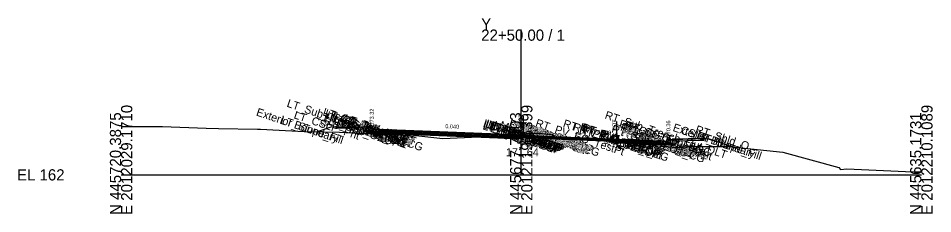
# Model space of a CAD drawing. Extents: x -26 to 3203, y -10 to 9532.
# Drawn here: x 974.3 to 1202.8, y 6490.3 to 6539.1 of the extents above; entities that cross this region are included whole.
import ezdxf

# ---------------------------------------------------------------- set-up
doc = ezdxf.new("R2010")
doc.units = 0
for name, color, linetype in [('Default', 7, 'Continuous'), ('Exist Cross Section Cell', 7, 'Continuous'), ('Exist XS Center Line Elevation Label', 7, 'Continuous'), ('Exist XS Ground Line', 7, 'Continuous'), ('Prop CMT Conc Surface', 7, 'Continuous'), ('Prop CMT Concrete Structures', 7, 'Continuous'), ('Prop CMT Pvmt Course 1', 7, 'Continuous'), ('Prop CMT Pvmt Course 1 CG', 7, 'Continuous'), ('Prop CMT Pvmt Course 1 Wedge', 7, 'Continuous'), ('Prop CMT Pvmt Course 2', 7, 'Continuous'), ('Prop CMT Pvmt Course 2 Wedge', 7, 'Continuous'), ('Prop CMT Pvmt Course 3', 7, 'Continuous'), ('Prop CMT Pvmt Course 3 Wedge', 7, 'Continuous'), ('Prop CMT Pvmt Surface', 7, 'Continuous'), ('Prop CMT Pvmt Wedge Surface 1', 7, 'Continuous'), ('Prop CMT Pvmt Wedge Surface 2', 7, 'Continuous'), ('Prop CMT Pvmt Wedge Surface 3', 7, 'Continuous'), ('Prop CMT Slope Grass', 7, 'Continuous'), ('Prop CMT Subgrade Earthwork', 7, 'Continuous'), ('Prop XS Hydro Elevations', 7, 'Continuous'), ('Prop XS Label Text', 7, 'Continuous'), ('Prop XS SE Text', 7, 'Continuous'), ('Prop XS Side Slope Text', 7, 'Continuous'), ('Scratch_Level_0', 7, 'Continuous')]:
    doc.layers.add(name, color=color, linetype=linetype)

msp = doc.modelspace()

# ---------------------------------------------------------------- linework, layer by layer
at = {"layer": 'Exist Cross Section Cell'}
for p, q in [((1100, 6500), (1100, 6536.29)), ((1000, 6500), (1100, 6500)), ((1100, 6500), (1200, 6500))]:
    msp.add_line(p, q, dxfattribs=at)
at = {"layer": 'Exist XS Ground Line'}
msp.add_lwpolyline([(1000, 6512.07), (1003.64, 6512.06), (1010.33, 6512.1), (1021.27, 6511.7), (1024.36, 6511.59), (1034.12, 6511.4), (1034.82, 6511.39), (1045.76, 6510.83), (1050.58, 6510.76), (1054.55, 6510.69), (1066.17, 6510.09), (1074.44, 6509.73), (1080.45, 6509.07), (1089.43, 6509.51), (1098.06, 6509.69), (1099, 6509.67), (1100.05, 6509.64), (1100.49, 6509.62), (1101.28, 6509.58), (1102.65, 6509.51), (1104.5, 6509.42), (1105.41, 6509.37), (1106.4, 6509.32), (1107.61, 6509.26), (1108.17, 6509.22), (1109.75, 6509.14), (1110.93, 6509.07), (1111.37, 6509.05), (1112.14, 6509.01), (1112.79, 6508.98), (1113.68, 6508.93), (1114.97, 6508.86), (1116.44, 6508.78), (1116.96, 6508.75), (1118.1, 6508.69), (1118.84, 6508.65), (1119.19, 6508.63), (1120.73, 6508.53), (1121.95, 6508.44), (1123.84, 6508.32), (1124.4, 6508.27), (1124.95, 6508.18), (1138.53, 6506.87), (1143.3, 6507.09), (1151.81, 6507.06), (1165.4, 6505.69), (1179.39, 6501.88), (1179.81, 6501.37), (1181.41, 6501.47), (1196.07, 6500.83), (1198.26, 6500.74), (1200, 6500.75)], dxfattribs=at)
at = {"layer": 'Prop CMT Conc Surface'}
for points in [[(1058.75, 6511.9), (1053.75, 6512)], [(1062.66, 6511.32), (1062.65, 6511.82), (1062.15, 6511.82)], [(1064.66, 6511.32), (1062.66, 6511.32)], [(1136.75, 6508.36), (1136.75, 6508.86), (1137.25, 6508.86)], [(1134.75, 6508.52), (1136.75, 6508.36)]]:
    msp.add_lwpolyline(points, dxfattribs=at)
at = {"layer": 'Prop CMT Concrete Structures'}
for points in [[(1053.75, 6511.67), (1053.75, 6512)], [(1053.75, 6512), (1058.75, 6511.9)], [(1058.75, 6511.57), (1053.75, 6511.67)], [(1058.75, 6511.9), (1058.75, 6511.57)], [(1064.66, 6511.32), (1062.66, 6511.32), (1062.65, 6511.82), (1062.15, 6511.82)], [(1062.15, 6511.82), (1062.16, 6510.84), (1064.66, 6510.74)], [(1064.66, 6510.74), (1064.66, 6511.32)], [(1108.33, 6509.57), (1108.32, 6509.74), (1107.57, 6509.99), (1104.55, 6510.35), (1101.54, 6510.29), (1100.79, 6510.04), (1100.78, 6509.88)], [(1100.78, 6509.88), (1108.33, 6509.57)], [(1134.75, 6508.52), (1136.75, 6508.36), (1136.75, 6508.86), (1137.25, 6508.86)], [(1137.25, 6508.86), (1137.25, 6507.83), (1134.75, 6507.93)], [(1145.75, 6509.04), (1137.75, 6508.88)], [(1137.75, 6508.88), (1137.75, 6508.54)], [(1137.75, 6508.54), (1145.75, 6508.7)], [(1145.75, 6508.7), (1145.75, 6509.04)], [(1134.75, 6507.93), (1134.75, 6508.52)]]:
    msp.add_lwpolyline(points, dxfattribs=at)
at = {"layer": 'Prop CMT Pvmt Course 1'}
for points in [[(1100.78, 6509.88), (1064.66, 6511.32)], [(1064.66, 6511.32), (1064.66, 6511.07)], [(1064.66, 6511.07), (1100.78, 6509.63)], [(1100.49, 6509.64), (1100.49, 6509.89)], [(1100.49, 6509.64), (1100.49, 6509.89)], [(1100.78, 6509.88), (1108.33, 6509.57)], [(1108.33, 6509.32), (1100.78, 6509.63)], [(1108.33, 6509.57), (1108.33, 6509.32)], [(1108.33, 6509.57), (1134.75, 6508.52)], [(1108.33, 6509.32), (1108.33, 6509.57)], [(1123.84, 6508.83), (1108.33, 6509.45)], [(1108.33, 6509.45), (1108.33, 6509.32), (1108.33, 6509.32)], [(1123.84, 6508.7), (1123.84, 6508.83)], [(1134.75, 6508.27), (1123.84, 6508.7)], [(1134.75, 6508.52), (1134.75, 6508.27)]]:
    msp.add_lwpolyline(points, dxfattribs=at)
msp.add_lwpolyline([(1100.49, 6509.64), (1100.49, 6509.76), (1100.49, 6509.76), (1100.49, 6509.64)], close=True, dxfattribs=at)
at = {"layer": 'Prop CMT Pvmt Course 1 CG'}
for points in [[(1064.66, 6510.74), (1061.66, 6510.86), (1061.33, 6510.54)], [(1061.33, 6510.54), (1064.66, 6510.4)], [(1064.66, 6510.4), (1064.66, 6510.74)], [(1134.75, 6507.93), (1137.75, 6507.81), (1138.1, 6507.47)], [(1134.75, 6507.6), (1134.75, 6507.93)], [(1138.1, 6507.47), (1134.75, 6507.6)]]:
    msp.add_lwpolyline(points, dxfattribs=at)
at = {"layer": 'Prop CMT Pvmt Course 1 Wedge'}
for points in [[(1100.49, 6509.76), (1109.75, 6509.39), (1110.93, 6509.34), (1111.37, 6509.33), (1112.14, 6509.3), (1112.79, 6509.27), (1113.68, 6509.23), (1114.97, 6509.18), (1116.44, 6509.12), (1116.96, 6509.1), (1118.1, 6509.06), (1118.84, 6509.03), (1119.19, 6509.01), (1120.73, 6508.95), (1121.95, 6508.9), (1123.84, 6508.83)], [(1108.33, 6509.32), (1108.33, 6509.45)], [(1123.84, 6508.7), (1123.59, 6508.71), (1121.95, 6508.78), (1120.73, 6508.83), (1119.19, 6508.89), (1118.84, 6508.9), (1118.1, 6508.93), (1116.96, 6508.98), (1116.44, 6509), (1114.97, 6509.06), (1113.68, 6509.11), (1112.79, 6509.15), (1112.14, 6509.17), (1111.37, 6509.2), (1110.93, 6509.22), (1109.75, 6509.27), (1108.33, 6509.32)], [(1123.84, 6508.83), (1123.84, 6508.7), (1123.84, 6508.7)]]:
    msp.add_lwpolyline(points, dxfattribs=at)
at = {"layer": 'Prop CMT Pvmt Course 2'}
for points in [[(1100.78, 6509.63), (1064.66, 6511.07)], [(1064.66, 6511.07), (1064.66, 6510.74)], [(1064.66, 6510.74), (1100.49, 6509.3)], [(1100.49, 6509.3), (1100.49, 6509.64)], [(1100.49, 6509.3), (1100.49, 6509.64)], [(1100.78, 6509.63), (1108.33, 6509.32)], [(1123.84, 6508.37), (1123.84, 6508.7)], [(1123.84, 6508.7), (1134.75, 6508.27)], [(1134.75, 6507.93), (1123.84, 6508.37)], [(1134.75, 6508.27), (1134.75, 6507.93)]]:
    msp.add_lwpolyline(points, dxfattribs=at)
at = {"layer": 'Prop CMT Pvmt Course 2 Wedge'}
for points in [[(1108.33, 6509.22), (1108.33, 6509.32)], [(1108.33, 6509.32), (1109.75, 6509.27), (1110.93, 6509.22), (1111.37, 6509.2), (1112.14, 6509.17), (1112.79, 6509.15), (1113.68, 6509.11), (1114.97, 6509.06), (1116.44, 6509), (1116.96, 6508.98), (1118.1, 6508.93), (1118.84, 6508.9), (1119.19, 6508.89), (1120.73, 6508.83), (1121.95, 6508.78), (1123.59, 6508.71), (1123.84, 6508.7)], [(1123.84, 6508.37), (1123.59, 6508.38), (1121.95, 6508.45), (1121.91, 6508.45), (1120.73, 6508.53), (1119.19, 6508.63), (1118.84, 6508.65), (1118.1, 6508.69), (1116.96, 6508.75), (1116.44, 6508.78), (1114.97, 6508.86), (1113.68, 6508.93), (1112.79, 6508.98), (1112.14, 6509.01), (1111.37, 6509.05), (1110.93, 6509.07), (1109.75, 6509.14), (1108.33, 6509.22)], [(1123.84, 6508.7), (1123.84, 6508.37), (1123.84, 6508.37)]]:
    msp.add_lwpolyline(points, dxfattribs=at)
at = {"layer": 'Prop CMT Pvmt Course 3'}
for points in [[(1100.49, 6509.3), (1064.66, 6510.74)], [(1064.66, 6510.74), (1064.66, 6510.4)], [(1064.66, 6510.4), (1100.49, 6508.97)], [(1100.49, 6508.97), (1100.49, 6509.3)], [(1100.49, 6508.97), (1100.49, 6509.3)], [(1123.84, 6508.37), (1134.75, 6507.93)], [(1123.84, 6508.04), (1123.84, 6508.37)], [(1134.75, 6507.6), (1123.84, 6508.04)], [(1134.75, 6507.93), (1134.75, 6507.6)]]:
    msp.add_lwpolyline(points, dxfattribs=at)
at = {"layer": 'Prop CMT Pvmt Course 3 Wedge'}
for points in [[(1124.95, 6508.18), (1124.4, 6508.27), (1124.03, 6508.31), (1123.84, 6508.32), (1123.59, 6508.34), (1121.95, 6508.44), (1121.91, 6508.45)], [(1121.91, 6508.45), (1121.95, 6508.45)], [(1121.95, 6508.45), (1123.59, 6508.38), (1123.84, 6508.37)], [(1123.84, 6508.37), (1123.84, 6508.23), (1123.84, 6508.23)]]:
    msp.add_lwpolyline(points, dxfattribs=at)
at = {"layer": 'Prop CMT Pvmt Surface'}
for points in [[(1100.78, 6509.88), (1064.66, 6511.32)], [(1100.78, 6509.88), (1108.33, 6509.57)], [(1108.33, 6509.57), (1134.75, 6508.52)]]:
    msp.add_lwpolyline(points, dxfattribs=at)
at = {"layer": 'Prop CMT Pvmt Wedge Surface 1'}
for points in [[(1108.33, 6509.57), (1108.33, 6509.32), (1108.33, 6509.32), (1108.33, 6509.45)], [(1108.33, 6509.45), (1123.84, 6508.83)], [(1123.84, 6508.83), (1123.84, 6508.7)], [(1123.84, 6508.7), (1134.75, 6508.27)], [(1134.75, 6508.27), (1134.75, 6508.52)]]:
    msp.add_lwpolyline(points, dxfattribs=at)
at = {"layer": 'Prop CMT Pvmt Wedge Surface 2'}
for points in [[(1108.33, 6509.57), (1108.33, 6509.32)], [(1108.33, 6509.32), (1134.75, 6508.27)], [(1134.75, 6508.27), (1134.75, 6508.52)]]:
    msp.add_lwpolyline(points, dxfattribs=at)
at = {"layer": 'Prop CMT Pvmt Wedge Surface 3'}
for points in [[(1100.49, 6509.3), (1134.75, 6507.93)], [(1134.75, 6507.93), (1134.75, 6508.52)]]:
    msp.add_lwpolyline(points, dxfattribs=at)
at = {"layer": 'Prop CMT Slope Grass'}
for points in [[(1062.15, 6511.82), (1052.65, 6512.01), (1048.97, 6510.78)], [(1137.25, 6508.86), (1146.75, 6509.05)], [(1146.75, 6509.05), (1153.1, 6506.93)]]:
    msp.add_lwpolyline(points, dxfattribs=at)
at = {"layer": 'Prop CMT Subgrade Earthwork'}
for points in [[(1064.66, 6510.4), (1061.33, 6510.54), (1060.01, 6511.86)], [(1100.49, 6508.97), (1064.66, 6510.4)], [(1100.49, 6508.97), (1100.49, 6509.62)], [(1134.75, 6507.6), (1138.1, 6507.47), (1139.53, 6508.9)], [(1123.84, 6508.04), (1123.82, 6508.33)], [(1123.84, 6508.04), (1134.75, 6507.6)]]:
    msp.add_lwpolyline(points, dxfattribs=at)
at = {"layer": 'Prop XS Label Text'}
for p, q in [((1100.49, 6514.62), (1100.49, 6509.62)), ((1123.84, 6513.32), (1123.84, 6508.32))]:
    msp.add_line(p, q, dxfattribs=at)

# ---------------------------------------------------------------- texts
at = {"layer": 'Default'}
msp.add_text('-', height=0.0001, dxfattribs=at).set_placement((1000, 6500))
at = {"layer": 'Exist Cross Section Cell'}
for s, p in [('Y', (1090, 6536.29)), ('22+50.00 / 1', (1090, 6533.49)), ('EL 162', (974, 6498.6))]:
    msp.add_text(s, height=2.8, dxfattribs=at).set_placement(p)
for s, p in [('E 2012029.1710', (1002.8, 6490)), ('E 2012119.6399', (1102.8, 6490)), ('E 2012210.1089', (1202.8, 6490)), ('N 445720.3875', (1000, 6490)), ('N 445677.7803', (1100, 6490)), ('N 445635.1731', (1200, 6490))]:
    msp.add_text(s, height=2.8, rotation=90, dxfattribs=at).set_placement(p)
at = {"layer": 'Exist XS Center Line Elevation Label'}
msp.add_text('171.64', height=2, dxfattribs=at).set_placement((1096.2, 6504.64))
at = {"layer": 'Prop XS Hydro Elevations'}
for s, p in [('173.32', (1063.16, 6512.32)), ('170.36', (1137.25, 6509.36))]:
    msp.add_text(s, height=1, rotation=90, dxfattribs=at).set_placement(p)
at = {"layer": 'Prop XS Label Text'}
for p in [(1100.39, 6510.64), (1123.74, 6509.35)]:
    msp.add_text('E. EOT', height=1, rotation=90, dxfattribs=at).set_placement(p)
at = {"layer": 'Prop XS SE Text'}
for p in [(1081.01, 6511.67), (1119, 6510.18)]:
    msp.add_text('0.040', height=1, rotation=357.7094, dxfattribs=at).set_placement(p)
at = {"layer": 'Prop XS Side Slope Text'}
for rotation, p in [(18.4349, (1049.82, 6511.86)), (341.5651, (1149.03, 6509.08))]:
    msp.add_text('3:1', height=1, rotation=rotation, dxfattribs=at).set_placement(p)
at = {"layer": 'Scratch_Level_0'}
for s, p in [('LT_Sub_Trench_Out_DLT', (1041.26, 6517.06)), ('Exterior Boundary', (1033.61, 6514.85)), ('LT_CSLP_Pnt', (1043.02, 6514.17)), ('LT_CG1_Shelf_Out', (1048.58, 6514.16)), ('LT_CG_Top_Face', (1050.25, 6514.9)), ('LT_CG_Top_BOC', (1050.72, 6514.58)), ('LT_CG_Top_Gut', (1051.18, 6514.09)), ('RT_Sub_Trench_Out_DLT', (1120.74, 6514.11)), ('LT_Slope_Fill', (1039.66, 6512.83)), ('LT_CG_Bot_BOC', (1050.75, 6513.58)), ('LT_Sub_OEOP', (1051.64, 6512.72)), ('LT_Sub_OEOT_CG', (1052.36, 6513.45)), ('LT_CG_Bot_IE', (1054.77, 6512.98)), ('LT_Sub_OEOT', (1054.93, 6512.59)), ('LT_PV2_OEOT', (1055.02, 6513.23)), ('LT_PV3_OEOT', (1055.02, 6512.9)), ('LT_PV1_OEOT', (1055.55, 6513.3)), ('LT_Sub_OEEOP', (1090.23, 6511.42)), ('LT_PV2_OEEOP', (1090.32, 6512.06)), ('LT_PV3_OEEOP', (1090.32, 6511.73)), ('LT_PV1_OEEOP', (1090.85, 6512)), ('LT_PV2_IEEOP', (1090.93, 6511.85)), ('LT_PV1_IEEOP', (1091.47, 6511.8)), ('LT_PV2_PGL1', (1091.81, 6511.56)), ('LT_PV2_PGL', (1092.12, 6511.46)), ('LT_PV1_PGL', (1092.66, 6511.53)), ('MI_Face In', (1092.78, 6511.66)), ('MI_Top In', (1094.44, 6511.6)), ('RT_PV_IEEOP_EG', (1096.76, 6512.02)), ('MI_Crown', (1097.66, 6511.6)), ('RT_PV2_IEEOP', (1098.43, 6511.57)), ('MI_Face Out', (1098.77, 6511.87)), ('MI_Top Out', (1098.93, 6511.82)), ('RT_PV1_IEEOP', (1098.97, 6511.51)), ('MI_Bot Out', (1099.72, 6511.39)), ('RT_PV_EG_TestPt', (1103.39, 6512.13)), ('RT_PV_Sub_Tie_Out', (1110.29, 6512.01)), ('RT_CG_Top_Face', (1124.3, 6511.95)), ('RT_CG_Top_BOC', (1125.77, 6511.63)), ('LT_PV3_PGL1', (1091.81, 6511.23)), ('LT_PV4_PGL', (1092.12, 6510.79)), ('RT_PV3_IEEOP', (1098.43, 6511.23)), ('RT_PV2_PGL1', (1099.31, 6511.27)), ('RT_PV3_PGL1', (1099.31, 6510.94)), ('RT_PV2_PGL', (1099.63, 6511.17)), ('RT_PV3_PGL', (1099.63, 6510.84)), ('RT_PV4_PGL', (1099.63, 6510.5)), ('RT_PV1_PGL', (1100.17, 6511.24)), ('RT_PV_OEEOP_EG', (1112.77, 6511.19)), ('RT_Sub_OEEOP', (1114.36, 6510.47)), ('RT_PV2_OEEOP', (1114.45, 6511.11)), ('RT_PV3_OEEOP', (1114.45, 6510.77)), ('RT_PV1_OEEOP', (1114.99, 6511.05)), ('RT_Sub_OEOT_CG', (1122.41, 6510.66)), ('RT_CG1_Shelf_Out', (1124.63, 6511.13)), ('RT_CG_Bot_IE', (1124.82, 6510.19)), ('RT_Sub_OEOT', (1124.98, 6509.8)), ('RT_PV2_OEOT', (1125.07, 6510.44)), ('RT_PV3_OEOT', (1125.07, 6510.11)), ('RT_CG_Top_Gut', (1125.23, 6511.14)), ('RT_PV1_OEOT', (1125.6, 6510.51)), ('RT_CG_Bot_BOC', (1125.8, 6510.6)), ('RT_Sub_OEOP', (1128.35, 6509.66)), ('Exterior Boundary', (1137.73, 6511)), ('CSLP_Pnt', (1139.67, 6510.35)), ('RT_Shld_O', (1143.35, 6510.54)), ('RT_Slope_Fill', (1143.73, 6509))]:
    msp.add_text(s, height=2, rotation=341.5651, dxfattribs=at).set_placement(p)

doc.saveas('drawing.dxf')
